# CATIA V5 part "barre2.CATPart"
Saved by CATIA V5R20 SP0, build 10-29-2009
Part number: barre2
Bounding box of the stored display mesh (mm): x 0 to 10, y -15.074 to 380.432, z -46.174 to 338.035
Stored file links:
  D:\Dropbox\IAO_2012\IAO_2012_748_omeyer\omeyer\omeyer\barre2.CATPart
  U:\Projet IAO\omeyer\Catia\Ass_748_skl.CATProduct
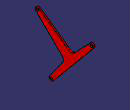
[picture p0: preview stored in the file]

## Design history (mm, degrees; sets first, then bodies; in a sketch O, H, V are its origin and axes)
Set1
  Plane1 "PlanRef": linked copy from another document
  DatumPoint1 "PointC": linked copy from another document
  Point1 "PointB": linked copy from another document
  DatumPoint2 "PointE": linked copy from another document
  Point2 "PointM": linked copy from another document
Body1 (main body)
  Sketch1 on Plane1, origin (0, 0, 0), H (0, 1, 0), V (0, 0, 1)
    point P1 (106.5265, -40.8035)
    line L1 (106.5265, -40.8035) -> (376.9493, 283.1649)
    arc A1 centre (365.4338, 292.7771) radius 15 from (376.9493, 283.1649) to (354.5999, 303.1514) ccw
    point P3 (365.4338, 292.7771)
    line L2 (354.5999, 303.1514) -> (252.0157, 196.0231)
    line L3 (213.1529, 192.1886) -> (8.5106, 335.3281)
    arc A2 centre (-0.0869, 323.0365) radius 15 from (8.5106, 335.3281) to (-10.644, 312.3807) ccw
    point P6 (-0.0869, 323.0365)
    line L4 (-10.644, 312.3807) -> (166.7645, 136.6149)
    line L5 (169.9373, 97.6926) -> (82.8675, -22.386)
    arc A3 centre (95.0111, -31.1913) radius 15 from (82.8675, -22.386) to (106.5265, -40.8035) ccw
    point P9 (95.0111, -31.1913)
    arc A4 centre (230.3479, 216.7718) radius 30 from (252.0157, 196.0231) to (213.1529, 192.1886) cw
    point P12 (230.3479, 216.7718)
    arc A5 centre (145.6502, 115.3033) radius 30 from (166.7645, 136.6149) to (169.9373, 97.6926) cw
    point P15 (145.6502, 115.3033)
    reference projected point E1 (365.4338, 292.7771) from DatumPoint1
    reference projected point E2 (95.0111, -31.1913) from Point1
    reference projected point E3 (-0.0869, 323.0365) from DatumPoint2
    point P16 (106.5265, -40.8035)
    circle A6 centre (365.4338, 292.7771) radius 7.5
    point P17 (365.4338, 292.7771)
    point P18 (-0.0869, 323.0365)
    circle A7 centre (-0.0869, 323.0365) radius 7.5
    circle A8 centre (95.0111, -31.1913) radius 7.5
    point P19 (95.0111, -31.1913)
    reference projected point E4 (365.4338, 292.7771) from DatumPoint1
    reference projected point E5 (95.0111, -31.1913) from Point1
    reference projected point E6 (-0.0869, 323.0365) from DatumPoint2
    radius A4 = 30
    radius A5 = 30
    radius A1 = 15
    radius A3 = 15
    radius A2 = 15
    distance P12 L1 = 70
    distance P15 L1 = 70
    distance P12 A1 = 170
    distance P15 A3 = 170
    radius A6 = 7.5
    radius A7 = 7.5
    radius A8 = 7.5
    tangency: A1 L1, A2 L3, A3 L5, A1 L2, A4 L2, A4 L3, A5 L4, A5 L5, A2 L4, L1 A3
    coincidence: P3 E1, P9 E2, P6 E3, P1 P16, P17 E4, P19 E5, P18 E6
  Pad1: profile Sketch1, direction (1, 0, 0), length 10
